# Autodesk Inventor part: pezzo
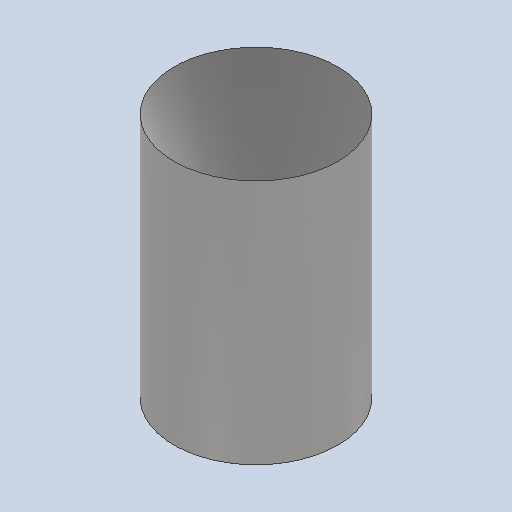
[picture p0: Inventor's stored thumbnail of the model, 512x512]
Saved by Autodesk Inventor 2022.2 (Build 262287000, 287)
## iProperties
Created: 2024-10
Part Number: pezzo
Material: Acciaio inossidabile
Document SubType Name: Modeling
Designer: 18907419
Density: 8 g/cm^3
Appearance: Default
Author: 18907419
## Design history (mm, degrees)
feature "Solido1"
node "Solido2"
